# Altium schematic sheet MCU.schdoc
size 309 x 209 mm
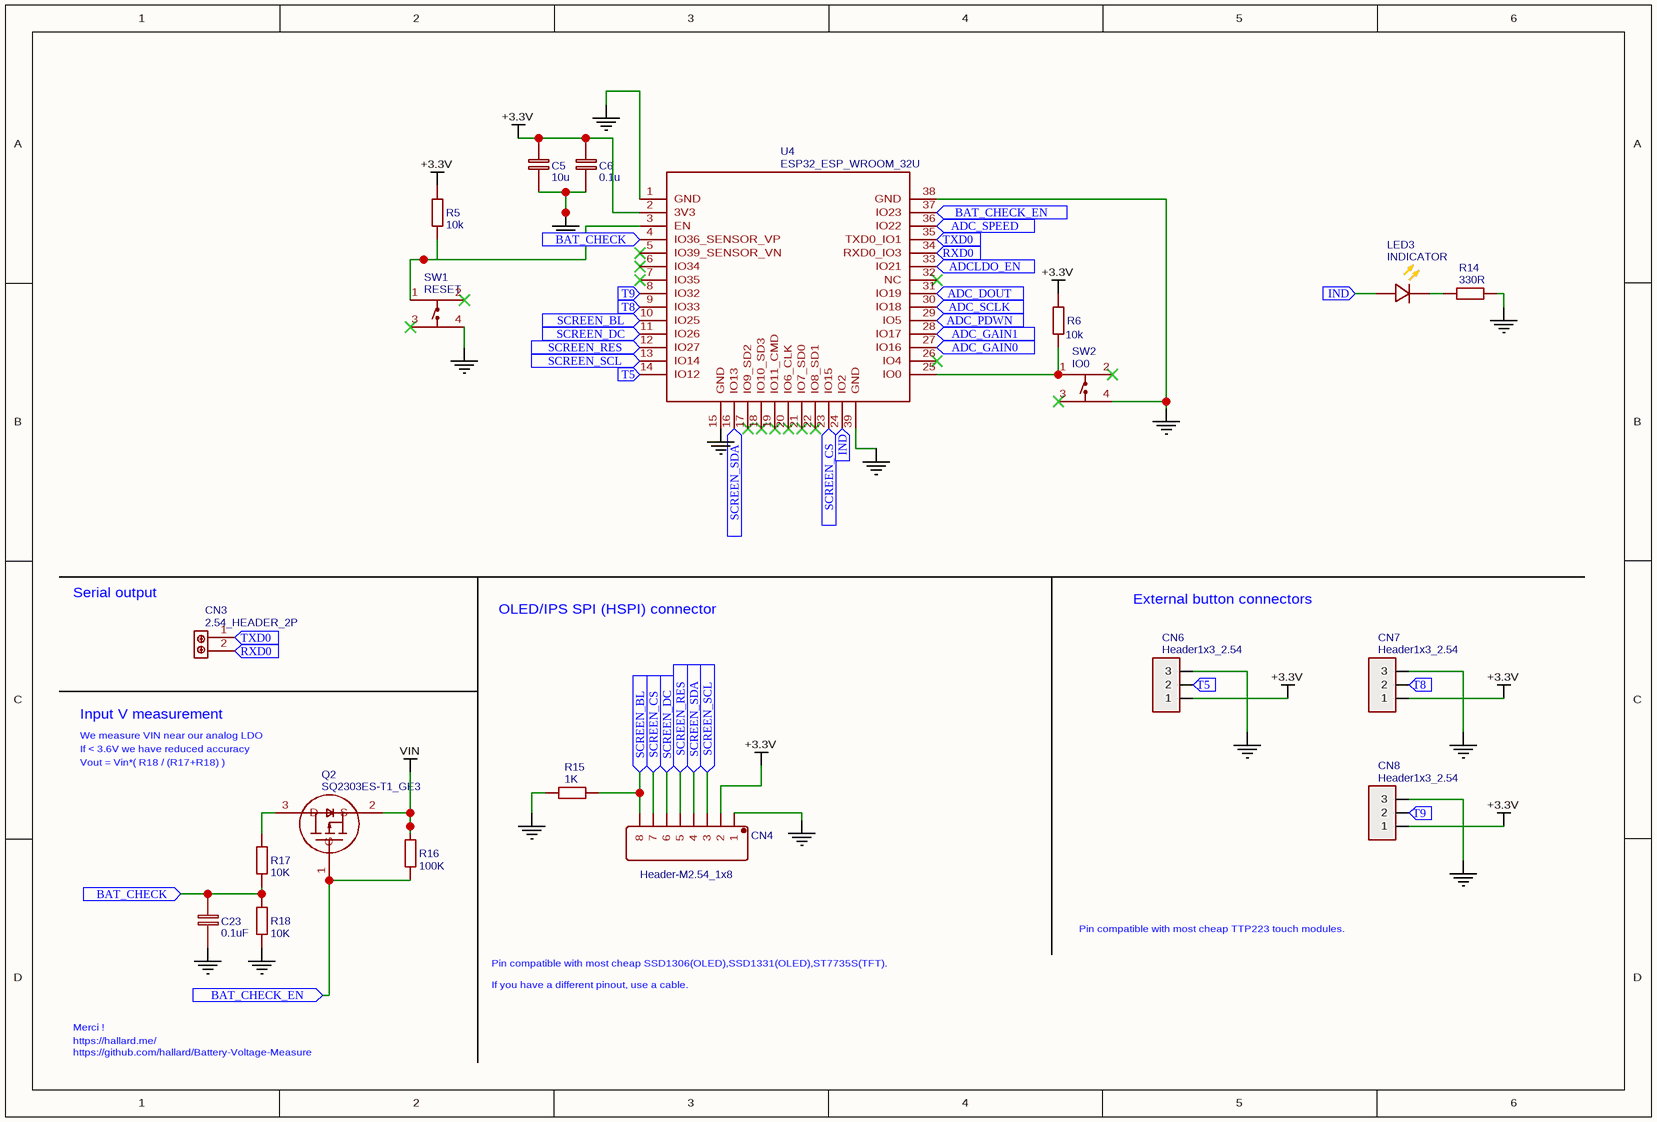
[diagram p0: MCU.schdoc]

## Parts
C5  10u  [0805]
C6  0.1u  [0805]
C23  0.1uF  [0805]
CN3  2.54_HEADER_2P  [2P_2.54]
CN4  Header-M2.54_1x8  [210S-1X8P]
CN6  Header1x3_2.54  [HDR-3X1/2.54]
CN7  Header1x3_2.54  [HDR-3X1/2.54]
CN8  Header1x3_2.54  [HDR-3X1/2.54]
LED3  INDICATOR  [LED-0805]
Q2  SQ2303ES-T1_GE3  [SOT-23(SOT-23-3)]
R5  10k  [0805]
R6  10k  [0805]
R14  330R  [0805]
R15  1K  [0805]
R16  100K  [0805]
R17  10K  [0805]
R18  10K  [0805]
SW1  RESET  [KEY-5.2X5.2X1.5]
SW2  IO0  [KEY-5.2X5.2X1.5]
U4  ESP32_ESP_WROOM_32U  [ESP32_ESP_WROOM_32U]

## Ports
ADC_DOUT, ADC_GAIN0, ADC_GAIN1, ADC_PDWN, ADC_SCLK, ADC_SPEED, ADCLDO_EN, BAT_CHECK, BAT_CHECK_EN, IND, RXD0, SCREEN_BL, SCREEN_CS, SCREEN_DC, SCREEN_RES, SCREEN_SCL, SCREEN_SDA, T5, T8, T9, TXD0

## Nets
+3.3V: C5.1 C6.1 CN4.2 CN6.1 CN7.1 CN8.1 U4.2(3V3)
GND: C5.2 C6.2 C23.2 CN4.1 CN6.3 CN7.3 CN8.3 SW1.4 SW2.4 U4.1(GND) U4.15(GND) U4.38(GND) U4.39(GND)
VIN: Q2.2(S)
ADC_DOUT: U4.31(IO19) ; port ADC_DOUT
ADC_GAIN0: U4.27(IO16) ; port ADC_GAIN0
ADC_GAIN1: U4.28(IO17) ; port ADC_GAIN1
ADC_PDWN: U4.29(IO5) ; port ADC_PDWN
ADC_SCLK: U4.30(IO18) ; port ADC_SCLK
ADC_SPEED: U4.36(IO22) ; port ADC_SPEED
ADCLDO_EN: U4.33(IO21) ; port ADCLDO_EN
BAT_CHECK: C23.1 U4.4(IO36_SENSOR_VP) ; port BAT_CHECK
BAT_CHECK_EN: Q2.1(G) U4.37(IO23) ; port BAT_CHECK_EN
IND: LED3.1(+) U4.24(IO2) ; port IND
RXD0: CN3.2 U4.34(RXD0_IO3) ; port RXD0
SCREEN_BL: CN4.8 U4.10(IO25) ; port SCREEN_BL
SCREEN_CS: CN4.7 U4.23(IO15) ; port SCREEN_CS
SCREEN_DC: CN4.6 U4.11(IO26) ; port SCREEN_DC
SCREEN_RES: CN4.5 U4.12(IO27) ; port SCREEN_RES
SCREEN_SCL: CN4.3 U4.13(IO14) ; port SCREEN_SCL
SCREEN_SDA: CN4.4 U4.16(IO13) ; port SCREEN_SDA
T5: CN6.2 U4.14(IO12) ; port T5
T8: CN7.2 U4.9(IO33) ; port T8
T9: CN8.2 U4.8(IO32) ; port T9
TXD0: CN3.1 U4.35(TXD0_IO1) ; port TXD0
NetSW1_1: SW1.1 U4.3(EN)
NetSW2_1: SW2.1 U4.25(IO0)

Not connected (* = marked no-connect by the designer): LED3 2(-); Q2 3(D); R5 1 2; R6 1 2; R14 1 2; R15 1 2; R16 1 2; R17 1 2; R18 1 2; SW1 2* 3*; SW2 2* 3*; U4 5(IO39_SENSOR_VN)* 6(IO34)* 7(IO35)* 17(IO9_SD2)* 18(IO10_SD3)* 19(IO11_CMD)* 20(IO6_CLK)* 21(IO7_SD0)* 22(IO8_SD1)* 26(IO4)* 32(NC)*

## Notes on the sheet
- Serial output
- External button connectors
- OLED/IPS SPI (HSPI) connector
- Input V measurement
- We measure VIN near our analog LDO
- If < 3.6V we have reduced accuracy
- Vout = Vin*( R18 / (R17+R18) )
- Pin compatible with most cheap TTP223 touch modules.
- Pin compatible with most cheap SSD1306(OLED),SSD1331(OLED),ST7735S(TFT).
- If you have a different pinout, use a cable.
- Merci !
- https://github.com/hallard/Battery-Voltage-Measure
- https://hallard.me/
- Labels drawn without touching a wire or pin: +3.3V, GND

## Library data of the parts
C5 = 10u: nameAlias: Value(F)
C6 = 0.1u: nameAlias: Value(F)
C23 = 0.1uF: nameAlias: Value(F)
CN3 = 2.54_HEADER_2P: Contributor: Tiberius Vinczi
CN4 = Header-M2.54_1x8: BOM_Manufacturer: Ckmtw; BOM_Manufacturer Part: 210S-1*8P L=11.6MMGold-plated black; Contributor: LCSC
CN6-CN8 = Header1x3_2.54: BOM_Manufacturer: EasyEDA; BOM_Manufacturer Part: Header-Male-2.54_1x3; BOM_EasyEDA: E49257; Contributor: kenankurt
LED3 = INDICATOR: BOM_Manufacturer: Hubei KENTO Elec; BOM_Manufacturer Part: 17-21SUYC/TR8
Q2 = SQ2303ES-T1_GE3: BOM_Manufacturer: VISHAY; Contributor: LCSC
R5 R6 = 10k: nameAlias: Value(Ω)
R14 = 330R: nameAlias: Value(Ω)
R15 = 1K: nameAlias: Value(Ω)
R16 = 100K: nameAlias: Value(Ω)
R17 R18 = 10K: nameAlias: Value(Ω)
SW1 = RESET: BOM_Manufacturer: C&K; BOM_Manufacturer Part: PTS525SM15SMTR2LFS; Contributor: LCSC
SW2 = IO0: BOM_Manufacturer: C&K; BOM_Manufacturer Part: PTS525SM15SMTR2LFS; Contributor: LCSC
U4 = ESP32_ESP_WROOM_32U: BOM_Manufacturer: Espressif Systems; BOM_Manufacturer Part: ESP32-WROOM-32U; Contributor: Zambiorix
